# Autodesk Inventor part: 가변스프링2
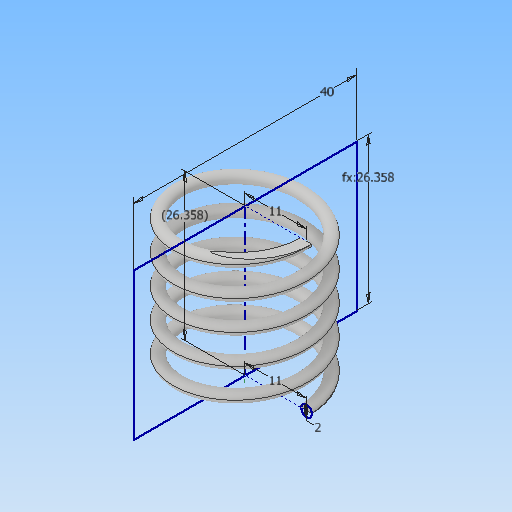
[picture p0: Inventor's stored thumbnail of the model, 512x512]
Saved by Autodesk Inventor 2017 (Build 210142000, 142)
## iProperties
Part Number: 가변스프링2
Material: 일반
Document SubType Name: Modeling
Designer: MRC
Density: 1 g/cm^3
Appearance: 기본값
Mass: 1.06846 g
Surface Area: 21.6623 cm^2
Volume: 1.06846 cm^3
Author: MRC
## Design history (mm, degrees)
sketch "스케치1"
  geometry: L1 (0, 0)-(0, 26.358); L2 (0, 0)-(11, 0); L3 (0, 26.358)-(11, 26.358); C1 r 1 at (11, 0)
  constraints: 6 end point, 2 horizontal, 1 centre point, 1 coincident, 1 vertical
  dimensions: "d0" = 11 distance of L1.start L2.end; "d1" = 11 distance of L1.end L3.end; "d2" = 2 diameter of C1; "d3" = 26.35829 distance of L1.start L1.end (derived)
feature "코일1" sketch "스케치1" pitch "d4" = 10; turns "d6" = 5; dims "d5" = 26.35829 (= d3), "d7" = 0, angle "d8" = 90 deg, angle "d9" = 90 deg, "d10" = 0, "d11" = 0
sketch "스케치2"
  geometry: L1 (26.358, 20)-(0, 20); L2 (0, 20)-(0, -20); L3 (0, -20)-(26.358, -20); L4 (26.358, -20)-(26.358, 20); 2 further points
  constraints: 8 end point, 2 parallel, 1 coincident, 1 horizontal, 1 midpoint, 1 perpendicular
  dimensions: "d13" = 26.35829 distance of L2.end L3.end (= d3); "d14" = 40 distance of L3.end L1.start
extrude "돌출1" sketch "스케치2" stored distance "d15" = 0; taper "d16" = 0 deg
node "솔리드1"
